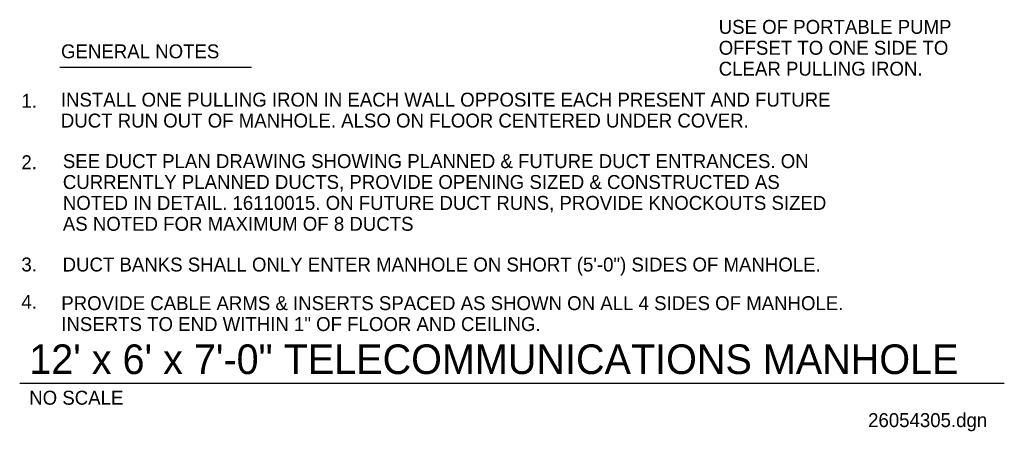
# Model space of a CAD drawing. Extents: x -12309 to -12261, y -12284 to -12184.
# Drawn here: x -12308.05 to -12260.9, y -12284.11 to -12264.42 of the extents above; entities that cross this region are included whole.
import ezdxf

# ---------------------------------------------------------------- set-up
doc = ezdxf.new("R2010")
doc.units = 0
doc.layers.add('G-ANNO-TEXT', color=7, linetype='Continuous')

msp = doc.modelspace()

# ---------------------------------------------------------------- linework, layer by layer
at = {"layer": 'G-ANNO-TEXT'}
for p, q in [((-12306.134, -12266.692), (-12296.947, -12266.692)), ((-12308.049, -12281.803), (-12260.904, -12281.803))]:
    msp.add_line(p, q, dxfattribs=at)

# ---------------------------------------------------------------- texts
for s, height, p in [('USE OF PORTABLE PUMP', 0.66667, (-12274.578, -12265.096)), ('OFFSET TO ONE SIDE TO', 0.66667, (-12274.578, -12266.096)), ('GENERAL NOTES', 0.66667, (-12306.07, -12266.266)), ('CLEAR PULLING IRON.', 0.66667, (-12274.578, -12267.096)), ('1.', 0.6667, (-12307.968, -12268.632)), ('INSTALL ONE PULLING IRON IN EACH WALL OPPOSITE EACH PRESENT AND FUTURE ', 0.66667, (-12306.079, -12268.578)), ('DUCT RUN OUT OF MANHOLE. ALSO ON FLOOR CENTERED UNDER COVER.', 0.66667, (-12306.079, -12269.578)), ('2.', 0.6667, (-12307.968, -12271.573)), ('SEE DUCT PLAN DRAWING SHOWING PLANNED & FUTURE DUCT ENTRANCES. ON', 0.66667, (-12305.984, -12271.518)), ('CURRENTLY PLANNED DUCTS, PROVIDE OPENING SIZED & CONSTRUCTED AS', 0.66667, (-12305.984, -12272.518)), ('NOTED IN DETAIL. 16110015. ON FUTURE DUCT RUNS, PROVIDE KNOCKOUTS SIZED', 0.66667, (-12305.984, -12273.518)), ('AS NOTED FOR MAXIMUM OF 8 DUCTS', 0.66667, (-12305.984, -12274.518)), ('3.', 0.6667, (-12307.968, -12276.463)), ('DUCT BANKS SHALL ONLY ENTER MANHOLE ON SHORT (5\'-0") SIDES OF MANHOLE.', 0.66667, (-12305.994, -12276.466)), ('4.', 0.6667, (-12307.968, -12278.249)), ('PROVIDE CABLE ARMS & INSERTS SPACED AS SHOWN ON ALL 4 SIDES OF MANHOLE. ', 0.66667, (-12306.058, -12278.314)), ('INSERTS TO END WITHIN 1" OF FLOOR AND CEILING.', 0.66667, (-12306.058, -12279.314)), ('12\' x 6\' x 7\'-0" TELECOMMUNICATIONS MANHOLE', 1.41667, (-12307.593, -12281.371)), ('NO SCALE', 0.6667, (-12307.593, -12282.838)), ('26054305.dgn', 0.66667, (-12267.425, -12283.91))]:
    msp.add_text(s, height=height, dxfattribs=at).set_placement(p)

doc.saveas('drawing.dxf')
